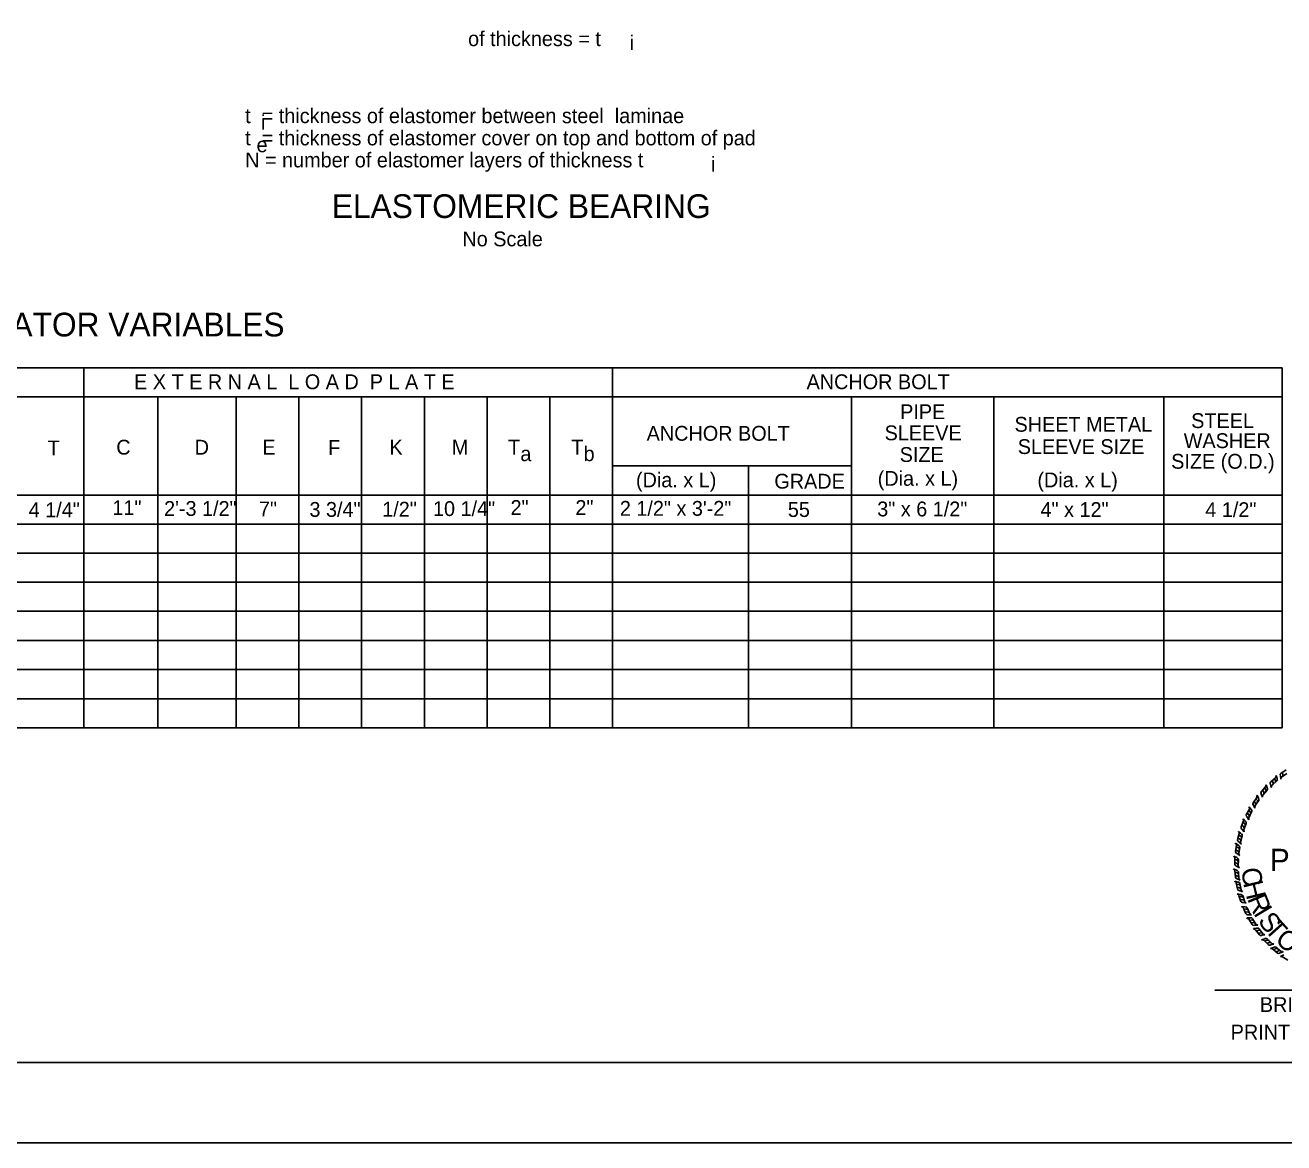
# Model space of a CAD drawing. Extents: x -193 to 149, y 507 to 725.
# Drawn here: x -47.9 to 58.2, y 507.1 to 601.4 of the extents above; entities that cross this region are included whole.
import ezdxf

# ---------------------------------------------------------------- set-up
doc = ezdxf.new("R2010")
doc.units = 0
for name, color, linetype in [('border', 7, 'Continuous'), ('Border 2660-Hwy18 - Level 62', 7, 'Continuous'), ('Border 2660-Hwy18 - Stamp-ChrisC', 7, 'Continuous'), ('Border 2660-Hwy18 - Text', 7, 'Continuous'), ('Level 40', 7, 'Continuous'), ('Level 41', 7, 'Continuous')]:
    doc.layers.add(name, color=color, linetype=linetype)

msp = doc.modelspace()

# ---------------------------------------------------------------- linework, layer by layer
at = {"layer": 'border'}
for p, q in [((52.39, 519.94), (73.81, 519.94)), ((143.78, 513.86), (-176.33, 513.86))]:
    msp.add_line(p, q, dxfattribs=at)
at = {"layer": 'Border 2660-Hwy18 - Level 62'}
msp.add_lwpolyline([(-192.53, 725.17), (148.65, 725.17), (148.65, 507.07), (-192.53, 507.07)], close=True, dxfattribs=at)
at = {"layer": 'Border 2660-Hwy18 - Stamp-ChrisC'}
for p, q in [((57.97, 538.24), (58.42, 538.54)), ((58.48, 538.24), (58.03, 537.92)), ((58.15, 538.12), (58.12, 538.32)), ((56.73, 537.27), (56.71, 537.25)), ((56.83, 537.03), (56.73, 537.27)), ((57.08, 537.36), (57.1, 537.32)), ((57.1, 537.32), (57.16, 537.05)), ((57.1, 537.32), (57.11, 537.29)), ((57.13, 537.53), (57.54, 537.89)), ((57.62, 537.6), (57.22, 537.23)), ((57.32, 537.44), (57.24, 537.64)), ((57.52, 537.62), (57.44, 537.8)), ((57.58, 538.07), (57.56, 538.04)), ((57.65, 537.81), (57.58, 538.07)), ((57.67, 537.77), (57.65, 537.81)), ((57.91, 538.07), (57.93, 538.03)), ((57.93, 538.03), (57.96, 537.76)), ((57.93, 538.03), (57.93, 538)), ((57.96, 537.76), (57.98, 537.8)), ((55.63, 535.76), (55.94, 536.2)), ((55.96, 536.39), (55.94, 536.36)), ((56.08, 536.15), (55.96, 536.39)), ((56.1, 536.1), (56.08, 536.15)), ((56.3, 536.54), (56.32, 536.49)), ((56.32, 536.49), (56.41, 536.23)), ((56.32, 536.49), (56.34, 536.47)), ((56.33, 536.71), (56.69, 537.1)), ((56.41, 536.23), (56.43, 536.27)), ((56.53, 536.63), (56.44, 536.81)), ((56.82, 536.82), (56.45, 536.41)), ((56.71, 536.83), (56.61, 537.01)), ((56.84, 536.98), (56.83, 537.03)), ((57.16, 537.05), (57.19, 537.09)), ((55.06, 534.75), (55.32, 535.23)), ((55.39, 534.98), (55.26, 535.13)), ((55.46, 535.2), (55.3, 535.42)), ((55.3, 535.42), (55.3, 535.38)), ((55.48, 535.16), (55.46, 535.2)), ((55.63, 535.58), (55.66, 535.55)), ((55.66, 535.55), (55.78, 535.31)), ((55.66, 535.55), (55.68, 535.52)), ((55.84, 535.71), (55.72, 535.89)), ((55.78, 535.31), (55.79, 535.36)), ((56.11, 535.94), (55.79, 535.49)), ((55.99, 535.94), (55.87, 536.1)), ((54.63, 533.72), (54.82, 534.23)), ((54.94, 533.97), (54.77, 534.11)), ((54.97, 534.21), (54.79, 534.4)), ((54.79, 534.4), (54.79, 534.37)), ((55.04, 534.01), (54.85, 533.5)), ((55, 534.17), (54.97, 534.21)), ((55.08, 534.59), (55.12, 534.56)), ((55.12, 534.56), (55.27, 534.33)), ((55.12, 534.56), (55.14, 534.53)), ((55.27, 534.74), (55.14, 534.9)), ((55.51, 535), (55.26, 534.5)), ((55.27, 534.33), (55.28, 534.38)), ((54.32, 532.64), (54.46, 533.16)), ((54.61, 533.16), (54.41, 533.34)), ((54.41, 533.34), (54.41, 533.3)), ((54.61, 532.93), (54.43, 533.04)), ((54.72, 532.97), (54.58, 532.43)), ((54.65, 533.12), (54.61, 533.16)), ((54.66, 533.55), (54.7, 533.51)), ((54.84, 533.72), (54.67, 533.86)), ((54.7, 533.51), (54.87, 533.31)), ((54.7, 533.51), (54.72, 533.5)), ((54.87, 533.31), (54.88, 533.36)), ((54.15, 531.64), (54.22, 532.17)), ((54.38, 532.19), (54.16, 532.34)), ((54.16, 532.34), (54.16, 532.31)), ((54.41, 531.96), (54.21, 532.05)), ((54.55, 532.67), (54.37, 532.79)), ((54.37, 532.48), (54.43, 532.46)), ((54.42, 532.16), (54.38, 532.19)), ((54.43, 532.46), (54.64, 532.27)), ((54.43, 532.46), (54.45, 532.43)), ((54.51, 532.01), (54.43, 531.47)), ((54.64, 532.27), (54.61, 532.31)), ((54.25, 531.14), (54.01, 531.26)), ((54.01, 531.26), (54.02, 531.23)), ((54.09, 530.57), (54.09, 531.11)), ((54.3, 530.91), (54.1, 530.99)), ((54.37, 531.69), (54.17, 531.8)), ((54.22, 531.48), (54.28, 531.47)), ((54.29, 531.11), (54.25, 531.14)), ((54.28, 531.47), (54.5, 531.3)), ((54.28, 531.47), (54.3, 531.45)), ((54.4, 530.98), (54.38, 530.43)), ((54.5, 531.3), (54.47, 531.35)), ((54.23, 530.07), (53.99, 530.18)), ((53.99, 530.18), (54, 530.14)), ((54.3, 530.65), (54.08, 530.72)), ((54.15, 529.49), (54.1, 530.03)), ((54.31, 529.85), (54.11, 529.91)), ((54.17, 530.42), (54.24, 530.4)), ((54.28, 530.05), (54.23, 530.07)), ((54.24, 530.4), (54.48, 530.27)), ((54.24, 530.4), (54.26, 530.39)), ((54.4, 529.93), (54.44, 529.38)), ((54.48, 530.27), (54.44, 530.3)), ((54.34, 529.07), (54.09, 529.14)), ((54.09, 529.14), (54.1, 529.12)), ((54.33, 529.58), (54.13, 529.64)), ((54.31, 528.49), (54.21, 529.01)), ((54.44, 528.86), (54.23, 528.89)), ((54.24, 529.34), (54.29, 529.34)), ((54.29, 529.34), (54.55, 529.23)), ((54.29, 529.34), (54.32, 529.34)), ((54.39, 529.06), (54.34, 529.07)), ((54.55, 529.23), (54.52, 529.27)), ((54.52, 528.95), (54.62, 528.41)), ((54.49, 528.59), (54.28, 528.63)), ((54.56, 528.03), (54.3, 528.08)), ((54.3, 528.08), (54.32, 528.05)), ((54.43, 528.35), (54.49, 528.35)), ((54.59, 527.44), (54.43, 527.95)), ((54.69, 527.84), (54.47, 527.84)), ((54.49, 528.35), (54.74, 528.26)), ((54.49, 528.35), (54.51, 528.35)), ((54.61, 528.02), (54.56, 528.03)), ((54.74, 528.26), (54.72, 528.31)), ((54.76, 527.93), (54.92, 527.4)), ((54.77, 527.58), (54.55, 527.6)), ((54.93, 526.97), (54.65, 527)), ((54.65, 527), (54.68, 526.97)), ((54.73, 527.33), (54.79, 527.34)), ((54.79, 527.34), (55.06, 527.28)), ((54.79, 527.34), (54.81, 527.33)), ((55.03, 526.39), (54.81, 526.88)), ((55.07, 526.8), (54.85, 526.77)), ((54.97, 526.97), (54.93, 526.97)), ((55.18, 526.55), (54.96, 526.54)), ((55.06, 527.28), (55.01, 527.32)), ((55.13, 526.9), (55.36, 526.39)), ((55.38, 526.04), (55.11, 526.04)), ((55.11, 526.04), (55.14, 526.01)), ((55.17, 526.3), (55.23, 526.31)), ((55.23, 526.31), (55.51, 526.29)), ((55.23, 526.31), (55.26, 526.31)), ((55.56, 525.48), (55.27, 525.94)), ((55.54, 525.88), (55.33, 525.83)), ((55.42, 526.05), (55.38, 526.04)), ((55.51, 526.29), (55.46, 526.32)), ((55.68, 525.65), (55.47, 525.62)), ((55.58, 525.98), (55.87, 525.51)), ((55.93, 525.17), (55.67, 525.14)), ((55.67, 525.14), (55.7, 525.11)), ((55.71, 525.41), (55.75, 525.43)), ((55.75, 525.43), (56.02, 525.43)), ((55.75, 525.43), (55.78, 525.42)), ((56.17, 524.62), (55.84, 525.05)), ((56.11, 525.02), (55.91, 524.96)), ((55.99, 525.18), (55.93, 525.17)), ((56.02, 525.43), (55.99, 525.47)), ((56.27, 524.8), (56.07, 524.75)), ((56.14, 525.13), (56.47, 524.68)), ((56.32, 524.56), (56.37, 524.58)), ((56.37, 524.58), (56.63, 524.61)), ((56.37, 524.58), (56.39, 524.59)), ((56.63, 524.61), (56.59, 524.64)), ((56.61, 524.29), (56.35, 524.21)), ((56.35, 524.21), (56.38, 524.2)), ((56.91, 523.79), (56.53, 524.17)), ((56.65, 524.31), (56.61, 524.29)), ((56.8, 524.17), (56.61, 524.08)), ((56.98, 523.97), (56.8, 523.9)), ((56.82, 524.28), (57.21, 523.88)), ((57.07, 523.75), (57.12, 523.77)), ((57.35, 523.56), (57.1, 523.47)), ((57.1, 523.47), (57.13, 523.45)), ((57.12, 523.77), (57.37, 523.84)), ((57.12, 523.77), (57.14, 523.79)), ((57.7, 523.08), (57.28, 523.43)), ((57.37, 523.84), (57.33, 523.87)), ((57.4, 523.58), (57.35, 523.56)), ((57.55, 523.46), (57.37, 523.35)), ((57.56, 523.57), (57.99, 523.22)), ((57.76, 523.28), (57.58, 523.19)), ((57.87, 523.06), (57.91, 523.1)), ((57.91, 523.1), (58.16, 523.19)), ((57.91, 523.1), (57.93, 523.1)), ((58.18, 522.9), (57.95, 522.78)), ((57.95, 522.78), (57.98, 522.76)), ((58.16, 523.19), (58.12, 523.2)), ((58.57, 522.47), (58.12, 522.77)), ((58.22, 522.92), (58.18, 522.9))]:
    msp.add_line(p, q, dxfattribs=at)
for centre, start, end in [((58.06, 538.12), 124.8528, 193.2267), ((56.57, 537.2), 322.2653, 21.0531), ((57.22, 537.42), 132.5627, 200.9367), ((57.33, 537.13), 136.8235, 195.6113), ((57.18, 537.39), 312.5627, 20.9367), ((57.37, 537.57), 312.5627, 20.9367), ((57.42, 538), 316.8235, 15.6113), ((57.52, 537.71), 312.5627, 20.9367), ((58.13, 537.82), 129.1135, 187.9014), ((58.01, 538.09), 304.8528, 13.2267), ((55.81, 536.28), 329.9636, 28.7515), ((56.44, 536.6), 138.0045, 206.3785), ((56.57, 536.32), 142.2653, 201.0531), ((56.39, 536.57), 318.0045, 26.3785), ((56.57, 536.76), 318.0045, 26.3785), ((56.71, 536.92), 318.0045, 26.3785), ((55.18, 535.3), 337.2243, 36.0121), ((55.38, 535.06), 332.9635, 41.3375), ((55.75, 535.68), 145.7028, 214.0768), ((55.92, 535.42), 149.9636, 208.7515), ((55.72, 535.64), 325.7028, 34.0768), ((55.86, 535.85), 325.7028, 34.0768), ((55.98, 536.02), 325.7028, 34.0768), ((54.67, 534.27), 343.6465, 42.4343), ((54.9, 534.06), 339.3857, 47.7597), ((55.2, 534.69), 152.9635, 221.3375), ((55.39, 534.46), 157.2243, 216.0121), ((55.16, 534.65), 332.9635, 41.3375), ((55.28, 534.88), 332.9635, 41.3375), ((54.32, 533.19), 350.445, 49.2329), ((54.51, 532.81), 346.1842, 54.5582), ((54.76, 533.67), 159.3857, 227.7597), ((54.56, 533.01), 346.1842, 54.5582), ((54.73, 533.62), 339.3857, 47.7597), ((54.98, 533.46), 163.6465, 222.4343), ((54.83, 533.87), 339.3857, 47.7597), ((54.08, 532.19), 356.646, 55.4338), ((54.47, 532.61), 166.1842, 234.5582), ((54.32, 531.83), 352.3852, 60.7592), ((54.35, 532.03), 352.3852, 60.7592), ((54.45, 532.55), 346.1842, 54.5582), ((54.72, 532.42), 170.445, 229.2329), ((53.95, 531.1), 3.9474, 62.7352), ((54.3, 531.62), 172.3852, 240.7592), ((54.23, 530.98), 359.6866, 68.0606), ((54.23, 530.77), 359.6866, 68.0606), ((54.29, 531.57), 352.3852, 60.7592), ((54.57, 531.47), 176.646, 235.4338), ((53.95, 530.01), 9.4933, 68.2812), ((54.24, 530.57), 179.6866, 248.0606), ((54.24, 529.91), 5.2325, 73.6065), ((54.23, 530.51), 359.6866, 68.0606), ((54.26, 529.71), 5.2325, 73.6065), ((54.52, 530.45), 183.9474, 242.7352), ((54.06, 528.98), 15.7912, 74.579), ((54.29, 529.5), 185.2325, 253.6065), ((54.28, 529.45), 5.2325, 73.6065), ((54.37, 528.92), 11.5304, 79.9044), ((54.41, 528.71), 11.5304, 79.9044), ((54.58, 529.41), 189.4933, 248.2812), ((54.46, 528.51), 191.5304, 259.9044), ((54.3, 527.91), 22.0938, 80.8817), ((54.46, 528.45), 11.5304, 79.9044), ((54.6, 527.88), 17.8331, 86.207), ((54.76, 528.45), 195.7912, 254.579), ((54.67, 527.69), 17.8331, 86.207), ((54.74, 527.49), 197.8331, 266.207), ((54.68, 526.82), 29.1451, 87.9329), ((54.75, 527.43), 17.8331, 86.207), ((55.05, 527.46), 202.0938, 260.8817), ((54.99, 526.83), 24.8843, 93.2583), ((55.07, 526.64), 24.8843, 93.2583), ((55.18, 526.4), 24.8843, 93.2583), ((55.17, 526.46), 204.8843, 273.2583), ((55.15, 525.86), 36.0034, 94.7913), ((55.48, 526.47), 209.1451, 267.9329), ((55.45, 525.91), 31.7427, 100.1166), ((55.56, 525.73), 31.7427, 100.1166), ((55.7, 525.51), 31.7427, 100.1166), ((55.98, 525.61), 216.0034, 274.7913), ((55.68, 525.56), 211.7427, 280.1166), ((55.72, 524.96), 40.9505, 99.7383), ((56.02, 525.04), 36.6897, 105.0637), ((56.15, 524.87), 36.6897, 105.0637), ((56.28, 524.71), 216.6897, 285.0637), ((56.3, 524.66), 36.6897, 105.0637), ((56.58, 524.79), 220.9505, 279.7383), ((56.42, 524.06), 49.2262, 108.0141), ((56.71, 524.18), 44.9655, 113.3394), ((56.86, 524.03), 44.9655, 113.3394), ((57.01, 523.89), 224.9655, 293.3394), ((57.04, 523.84), 44.9655, 113.3394), ((57.19, 523.32), 54.451, 113.2388), ((57.29, 524.01), 229.2262, 288.0141), ((57.47, 523.46), 50.1902, 118.5642), ((57.62, 523.33), 50.1902, 118.5642), ((57.79, 523.2), 230.1902, 298.5642), ((57.83, 523.16), 50.1902, 118.5642), ((58.06, 523.34), 234.451, 293.2388), ((58.05, 522.64), 60.4344, 119.2222)]:
    msp.add_arc(centre, 0.148, start, end, dxfattribs=at)
at = {"layer": 'Level 40'}
for p, q in [((-36.75, 570.01), (-36.75, 542.09)), ((-30.14, 570.01), (-30.14, 542.09)), ((-24.85, 570.01), (-24.85, 542.09)), ((-19.56, 570.01), (-19.56, 542.09)), ((-14.27, 570.01), (-14.27, 542.09)), ((-8.98, 570.01), (-8.98, 542.09)), ((-3.69, 570.01), (-3.69, 542.09)), ((0.21, 570.01), (5.33, 570.01)), ((21.76, 570.01), (21.76, 542.09)), ((33.76, 570.01), (33.76, 542.09)), ((48.11, 570.01), (48.11, 542.09)), ((1.6, 564.17), (21.76, 564.17)), ((13.08, 564.17), (13.08, 542.09)), ((-173.56, 561.72), (58.08, 561.72)), ((-43, 562.22), (-43, 558.73)), ((-36.75, 562.22), (-36.75, 558.73)), ((-30.14, 562.22), (-30.14, 558.73)), ((-24.85, 562.22), (-24.85, 558.73)), ((1.6, 562.22), (1.6, 558.73)), ((21.76, 562.22), (21.76, 558.73)), ((33.76, 562.22), (33.76, 558.73)), ((48.11, 562.22), (48.11, 558.73)), ((-173.56, 559.27), (58.08, 559.27)), ((-173.56, 556.81), (58.08, 556.81)), ((-173.56, 556.81), (58.08, 556.81)), ((-43, 557.31), (-43, 553.82)), ((-36.75, 557.31), (-36.75, 553.82)), ((-30.14, 557.31), (-30.14, 553.82)), ((-24.85, 557.31), (-24.85, 553.82)), ((1.6, 557.31), (1.6, 553.82)), ((21.76, 557.31), (21.76, 553.82)), ((33.76, 557.31), (33.76, 553.82)), ((48.11, 557.31), (48.11, 553.82)), ((-173.56, 554.36), (58.08, 554.36)), ((-173.56, 554.36), (58.08, 554.36)), ((-173.56, 551.91), (58.08, 551.91)), ((-173.56, 551.91), (58.08, 551.91)), ((-173.56, 549.45), (58.08, 549.45)), ((-173.56, 547), (58.08, 547)), ((-173.56, 544.54), (58.08, 544.54))]:
    msp.add_line(p, q, dxfattribs=at)
at = {"layer": 'Level 41'}
for p, q in [((-92.48, 572.46), (58.08, 572.46)), ((-43, 572.46), (-43, 542.09)), ((1.6, 572.46), (1.6, 542.09)), ((58.08, 572.46), (58.08, 542.09)), ((-173.56, 570.01), (58.08, 570.01)), ((-173.56, 542.09), (58.08, 542.09))]:
    msp.add_line(p, q, dxfattribs=at)

# ---------------------------------------------------------------- texts
at = {"layer": 'Border 2660-Hwy18 - Stamp-ChrisC'}
msp.add_text('PROFESSIONAL', height=1.875, dxfattribs=at).set_placement((57.05, 530))
for s, rotation, p in [('C', 275.4459, (54.66, 530.23)), ('H', 283.4739, (54.78, 529)), ('R', 292.3405, (55.11, 527.67)), ('I', 300.9555, (55.62, 526.44)), ('S', 305.713, (55.98, 525.8)), ('T', 311.8122, (56.52, 525.03)), ('O', 320.3433, (57.4, 524.05))]:
    msp.add_text(s, height=1.64, rotation=rotation, dxfattribs=at).set_placement(p)
at = {"layer": 'Border 2660-Hwy18 - Text'}
for s, p in [('BRIDGE ENGINEER', (56.2, 518.11)), ('PRINT DATE:', (53.74, 515.79))]:
    msp.add_text(s, height=1.25, dxfattribs=at).set_placement(p)
at = {"layer": 'Level 40'}
for s, p in [('of thickness = t', (-10.58, 599.59)), ('t  = thickness of elastomer between steel  laminae', (-29.38, 593.09)), ('t  = thickness of elastomer cover on top and bottom of pad', (-29.38, 591.22)), ('e', (-28.42, 590.64)), ('N = number of elastomer layers of thickness t', (-29.38, 589.36)), ('No Scale', (-11.06, 582.7)), ('E X T E R N A L  L O A D  P L A T E ', (-38.75, 570.65)), ('ANCHOR BOLT', (17.97, 570.65)), ('PIPE', (25.86, 568.12)), ('SHEET METAL', (35.51, 567.06)), ('STEEL', (50.41, 567.37)), ('ANCHOR BOLT', (4.48, 566.3)), ('SLEEVE', (24.55, 566.34)), ('WASHER', (49.78, 565.68)), ('T', (-46.04, 565.07)), ('C', (-40.25, 565.13)), ('D', (-33.64, 565.13)), ('E', (-27.93, 565.13)), ('F', (-22.38, 565.1)), ('K', (-17.22, 565.13)), ('M', (-11.95, 565.13)), ('T ', (-7.21, 565.13)), ('T ', (-1.88, 565.13)), ('b ', (-0.84, 564.58)), ('SLEEVE SIZE', (35.78, 565.18)), ('a ', (-6.17, 564.58)), ('SIZE', (25.82, 564.51)), ('SIZE (O.D.)', (48.72, 563.94)), ('(Dia. x L)', (23.97, 562.5)), ('(Dia. x L)', (3.58, 562.37)), ('GRADE', (15.25, 562.26)), ('(Dia. x L)', (37.44, 562.37)), ('4 1/4"', (-47.64, 559.85)), ('11"', (-40.58, 560.03)), ('2\'-3 1/2"', (-36.22, 559.96)), ('7"', (-28.22, 559.92)), ('3 3/4"', (-23.96, 559.88)), ('1/2"', (-17.82, 559.9)), ('10 1/4"', (-13.54, 559.95)), ('2"', (-7, 560.04)), ('2"', (-1.53, 560.04)), ('2 1/2" x 3\'-2"', (2.22, 559.97)), ('55', (16.39, 559.87)), ('3" x 6 1/2"', (23.93, 559.92)), ('4" x 12"', (37.7, 559.87)), ('4 1/2"', (51.6, 559.86))]:
    msp.add_text(s, height=1.25, dxfattribs=at).set_placement(p)
for p in [(3.04, 599.25), (-28.05, 592.53), (9.9, 589.01)]:
    msp.add_text('i', height=1.25, rotation=360, dxfattribs=at).set_placement(p)
at = {"layer": 'Level 41'}
for s, p in [(' ELASTOMERIC BEARING ', (-22.82, 585.09)), (' TABLE OF FABRICATOR VARIABLES ', (-73.32, 575.1))]:
    msp.add_text(s, height=2, dxfattribs=at).set_placement(p)

doc.saveas('drawing.dxf')
